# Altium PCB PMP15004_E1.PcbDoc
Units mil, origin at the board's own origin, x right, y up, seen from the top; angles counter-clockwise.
Board outline 993.36 x 993.36 mil, 2 copper layers (Top Layer, Bottom Layer), stack 62 mil thick; 37 components, 15 nets, 80 pads, 23 vias.
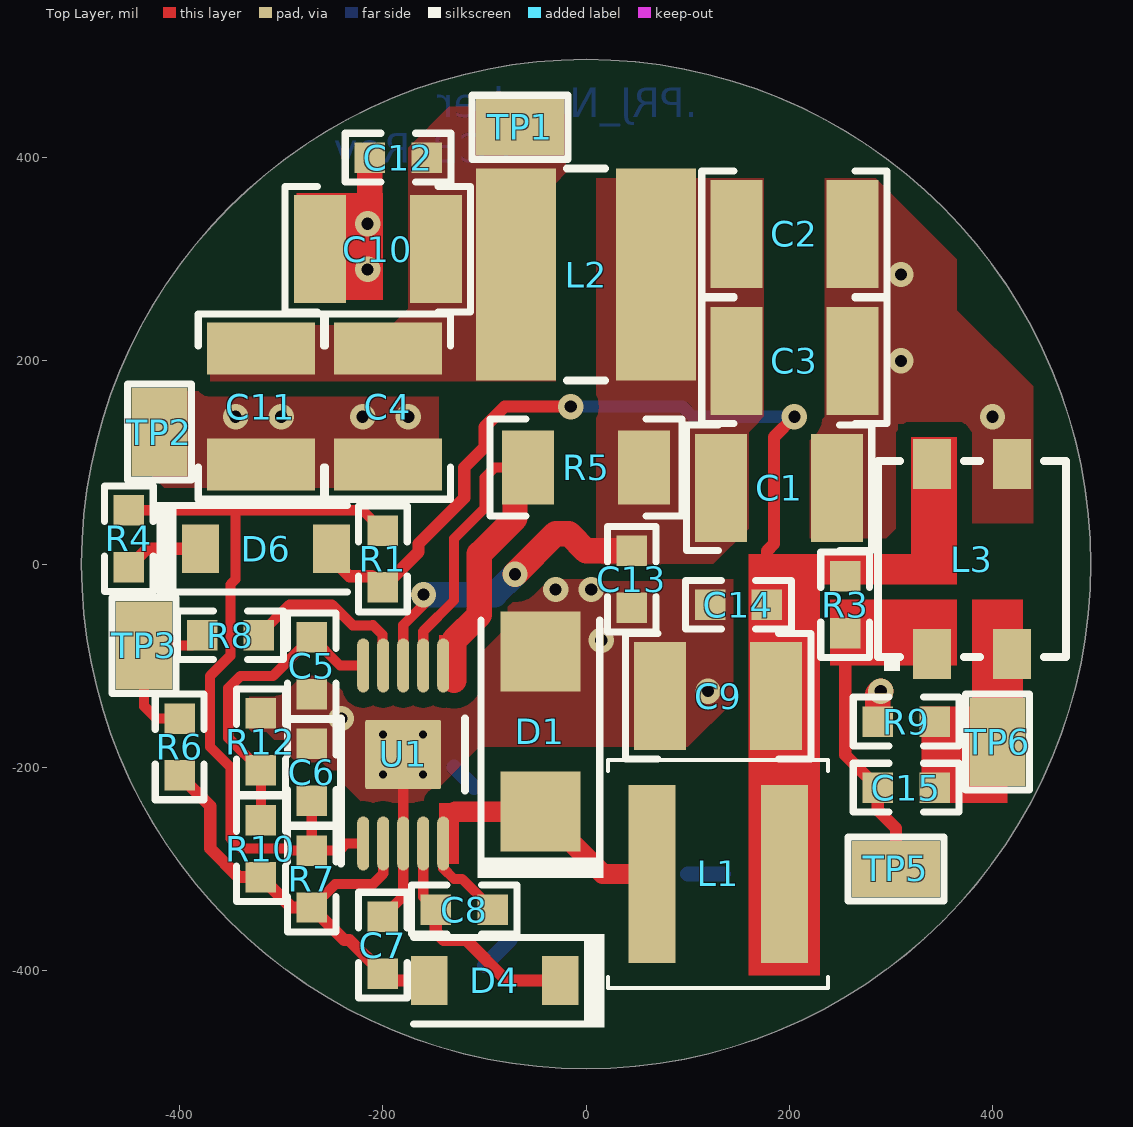
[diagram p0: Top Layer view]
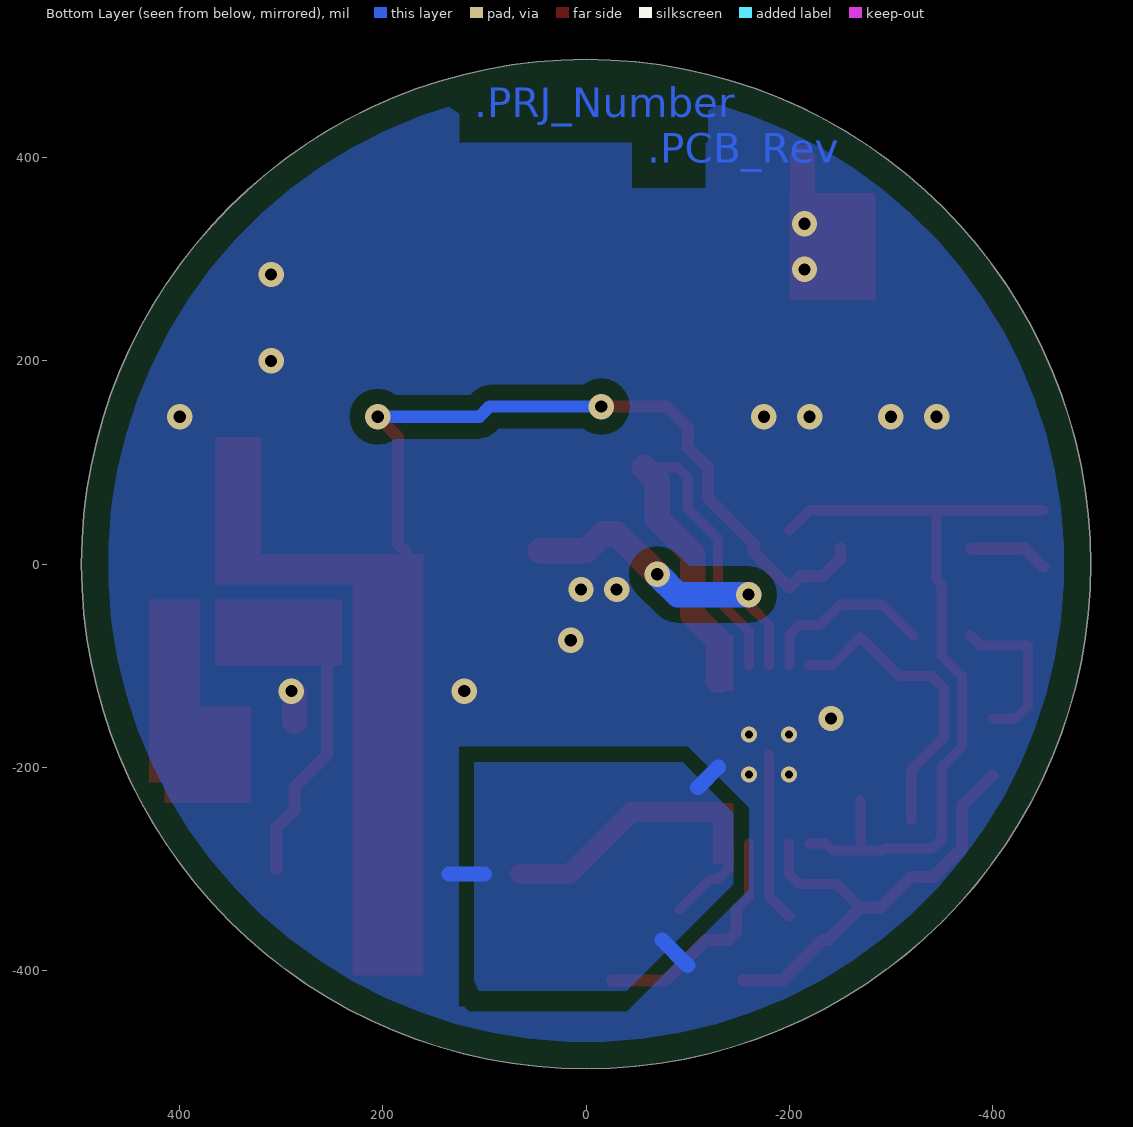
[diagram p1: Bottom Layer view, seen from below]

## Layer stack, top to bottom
Top Solder: solder mask 0.4, Solder Resist, Dk 3.5
Top Layer: signal copper 1.4
Dielectric1: core 59.2, FR-4, Dk 4.8
Bottom Layer: signal copper 1.4
Bottom Solder: solder mask 0.4, Solder Resist, Dk 3.5

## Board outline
0,-496.68 cw(c0,0) -496.68,0 cw(c0,0) 0,496.68 cw(c0,0) 496.68,0 cw(c0,0)

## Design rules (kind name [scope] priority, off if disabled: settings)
AcuteAngle [All] p1: minimum=4.50000000000000E+0001 checktracksonly=FALSE
AssemblyTestPointUsage [All] p1: valid=2
Clearance Clearance_BoardEdge [OnCopper and Not InComponentClass('Logo') and not InComponentClass('FiducialMark') and not InRegion(1000,500,4000,800) and Not IsKeepout vs IsKeepOut] p1: gap=15
Clearance Clearance_Poly [InPolygon] p2: gap=15
Clearance [All] p3: gap=7.87
ComponentClearance ComponentClearance_Logo [InComponentClass('Logo')] p1: gap=5 collisioncheckmode=3 verticalgap=10 showdistances=FALSE
ComponentClearance [All] p2: gap=5 collisioncheckmode=3 verticalgap=5 showdistances=FALSE
DiffPairsRouting [All] p1: maxlimit=100 minlimit=10 mostfreqgap=10 toplayer_minwidth=15 toplayer_maxwidth=15 toplayer_prefwidth=15 bottomlayer_minwidth=15 bottomlayer_maxwidth=15 bottomlayer_prefwidth=15 maxuncoupledlength=1000
FabricationTestPointUsage TestPointUsage [All] p1: valid=2 allowmultiple=FALSE
FabricationTestpoint Testpoint [All] p1: side=3 testpointundercomponent=TRUE minsize=40 maxsize=100 preferedsize=60 minholesize=0 maxholesize=40 preferedholesize=32 testpointgrid=1 allowsidetop=TRUE allowsidebottom=TRUE usegrid=TRUE gridtolerance=0.01
FanoutControl Fanout_LCC [IsLCC] p1: bgadir=Out bgaviamode=Centered fanoutstyle=Auto fanoutdirection=Alternating viagrid=1 // Fanout_LCC (Default Rule)
FanoutControl Fanout_BGA [IsBGA] p2: bgadir=Out bgaviamode=Centered fanoutstyle=Auto fanoutdirection=Alternating viagrid=1 // Fanout_BGA (Default Rule)
FanoutControl Fanout_Default [All] p4: bgadir=Out bgaviamode=Centered fanoutstyle=Auto fanoutdirection=Alternating viagrid=1 // Fanout_Default (Default Rule)
FanoutControl Fanout_Small [(CompPinCount < 5)] p5: bgadir=Out bgaviamode=Centered fanoutstyle=Auto fanoutdirection=OutThenIn viagrid=1 // Fanout_Small (Default Rule)
HoleSize [All] p1: absolutevalues=TRUE maxlimit=251 minlimit=7.87 maxpercent=80.000 minpercent=20.000
MinimumAnnularRing MinimumAnnularRing_ThermalPadVias [IsVia and InAnyComponent] p1: minimumring=3.94
MinimumAnnularRing [All] p2: minimumring=6.5
MinimumSolderMaskSliver MinimumSolderMaskSliver_Logo [InComponentClass('Logo') vs InComponentClass('Logo')] p1: minsoldermaskwidth=0.7
MinimumSolderMaskSliver [All] p2: minsoldermaskwidth=3.94
PlaneConnect [All] p1: planeconnectstyle=Relief reliefexpansion=10 reliefentries=4 reliefconductorwidth=10 reliefairgap=10
PolygonConnect PolygonConnect_direct [InNet('GND')or InNet('NetDRN_1')or InNet('VIN')or InNet('LED+')or InNet('NetRsense1_1')or InNet('NetR5_1')or InNet('NetC8_1')] p1: connectstyle=Direct reliefconductorwidth=10 reliefentries=4 polygonreliefangle="90 Angle" airgapwidth=10
PolygonConnect [All] p2: connectstyle=Direct reliefconductorwidth=10 reliefentries=4 polygonreliefangle="90 Angle" airgapwidth=10
RoutingVias [All] p1: holewidth=16 width=34 viastyle="Through Hole" minholewidth=7.87 minwidth=15.75 maxholewidth=40 maxwidth=65
SilkToBoardRegionClearance [Not ((IsComment or IsDesignator) And (Hide <> 'False')) and not InRegion(1000,500,4000,800)] p1:
SilkToSilkClearance SilkToSilkClearance_Pb-FreeLogo [(HasFootprint('Pb-Free_Overlay_Medium') OR HasFootprint('Pb-Free_Overlay_Small')) vs (HasFootprint('Pb-Free_Overlay_Medium') OR HasFootprint('Pb-Free_Overlay_Small'))] p1: silktosilkclearance=0
SilkToSilkClearance [All] p2: silktosilkclearance=4
SilkToSolderMaskClearance Inductors [IsPad] p1 off: minsilkscreentomaskgap=10 clearancetoexposedcopper=TRUE
SilkToSolderMaskClearance SilkToSolderMaskClearance_0603-095 [HasFootprint('0603_095')] p2 off: minsilkscreentomaskgap=1 clearancetoexposedcopper=TRUE
SilkToSolderMaskClearance SilkToSolderMaskClearance_discretes [IsPad AND InAnyComponent] p3 off: minsilkscreentomaskgap=5 clearancetoexposedcopper=TRUE
SilkToSolderMaskClearance [IsPad] p4 off: minsilkscreentomaskgap=5 clearancetoexposedcopper=TRUE
SilkToSolderMaskClearance "Silk to Solder Mask Opening" [IsVia vs InComponent('U1')] p5 off: minsilkscreentomaskgap=-1 clearancetoexposedcopper=FALSE
SolderMaskExpansion [All] p1: expansion=1.97
Width [All] p1: maxlimit=100 minlimit=6 preferedwidth=10 checkconnectedcopper=TRUE
15 further rules are at their usual default settings.

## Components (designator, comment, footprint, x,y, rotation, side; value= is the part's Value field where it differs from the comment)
C1 "GRM32ER71J106KA12L" 1210 190,75 r0 top
C2 "GRM32ER71J106KA12L" 1210 205,325 r0 top
C3 "GRM32ER71J106KA12L" 1210 205,200 r0 top
C4 "GRM32ER71J106KA12L" 1210 -195,155 r270 top
C5 "GCM188R71C104KA37J" 0603_HV -270,-100 r90 top
C6 "GCM1885C1H471JA16D" 0603_HV -270,-205 r90 top
C7 "GCM188R71C105KA64D" 0603_HV -200,-375 r90 top
C8 "GCM188R71C104KA37J" 0603_HV -120,-340 r180 top
C9 "CGA5L3X7S2A225M160AB" 1210 130,-130 r180 top
C10 "GRM32ER71J106KA12L" 1210 -205,310 r180 top
C11 "GRM32ER71J106KA12L" 1210 -320,155 r270 top
C12 "GRM188R72A104KA35D" 0603_HV -185,400 r180 top
C13 "GRM188R72A104KA35D" 0603_HV 45,-15 r270 top
C14 "GRM188R71E104KA01D" 0603_HV 150,-40 r180 top
C15 "GRM188R71E104KA01D" 0603_HV 315,-220 r0 top
D1 "RB058L-60TE25" SMA -45,-165 r90 top
D4 "MMSD4148T1G" SOD-123 -90,-410 r180 top
D6 "MMSD4148T1G" SOD-123 -315,15 r0 top
L1 "XAL5050-223MEB" XAL5050 130,-305 r0 top
L2 "74408943100" WE-SPC_4838 0,285 r0 top
L3 "ACM4520-421-2P-T000" TDK_ACM4520 379.71,5 r90 top
R1 "CRCW060324K9FKEA" 0603_HV -200,5 r90 top
R3 "CRCW06030000Z0EA" 0603_HV 255,-40 r270 top
R4 "CRCW060348K7FKEA" 0603_HV -450,25 r270 top
R5 "WSL1206R1500FEA" 1206 0,95 r0 top
R6 "CRCW060310K0FKEA" 0603_HV -400,-180 r90 top
R7 "CRCW0603309KFKEA" 0603_HV -270,-310 r90 top
R8 "CRCW060310K0FKEA" 0603_HV -350,-70 r0 top
R9 "CRCW06030000Z0EA" 0603_HV 315,-155 r0 top
R10 "CRCW0603100KFKEA" 0603_HV -320,-280 r270 top
R12 "CRCW060361K9FKEA" 0603_HV -320,-175 r270 top
TP1 "5015" S2751-46R -65,430 r0 top
TP2 "5015" S2751-46R -420,130 r270 top
TP3 "5015" S2751-46R -435,-80 r90 top
TP5 "5015" S2751-46R 305,-300 r180 top
TP6 "5015" S2751-46R 405,-175 r270 top
U1 "TPS92515HVQDGQRQ1" DGQ0010A_N -180,-187.4 r90 top

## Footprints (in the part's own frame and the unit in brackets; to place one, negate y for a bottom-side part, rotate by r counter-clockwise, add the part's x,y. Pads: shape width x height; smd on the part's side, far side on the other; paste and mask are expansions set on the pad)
0603_HV [mil] "Ernesto recommended land pattern.  26 mil between pads."
  rect 30x30 smd: 1(-28,0) 2(28,0)
  silkscreen extent -52,-24 52,24, body extent -34,-19 34,19, height 39
1206 [mm] "1206 from SM-752 data"
  rect 1.3x1.85 smd: 1(-1.45,0) 2(1.45,0)
  silkscreen extent -2.4,-1.21 2.4,1.21, body extent -1.7,-0.9 1.7,0.9, height 1.35
1210 [mm] "1210 from SM-752 data"
  rect 1.3x2.7 smd: 1(-1.45,0) 2(1.45,0)
  silkscreen extent -2.32,-1.57 2.32,1.57, body extent -1.7,-1.35 1.7,1.35, height 1.35
DGQ0010A_N [mm] "TSSOP, 10-Leads, Body 3x3mm, Pitch 0.5mm, Exposed Pad, IPC Medium Density"
  rrect100% 1.35x0.3 smd: 1(-2.225,1) 2(-2.225,0.5) 3(-2.225,0) 4(-2.225,-0.5) 5(-2.225,-1) 6(2.225,-1) 7(2.225,-0.5) 8(2.225,0) 9(2.225,0.5) 10(2.225,1)
  rrect6% 1.73x1.9 smd: 11(0,0)
  silkscreen extent -2.73,-1.55 0.9,1.55, body extent -2.45,-1.5 2.45,1.5, height 0.96
S2751-46R [mm] "Harwin P/N S2751-46R"
  rect 2.2x1.4 smd: 1(0,0)
  silkscreen extent -1.2,-0.8 1.2,0.8, body extent -1,-0.6 1,0.6, height 1.41
SMA [mm] "Molded Diode, 2-Leads, Body 4.3x2.6mm, IPC Medium Density, based on OnSemi component dimensions and land pattern"
  rect 2x2 smd: 1(-2,0) 2(2,0)
  silkscreen extent -3.66,-1.57 2.79,1.57, body extent -2.6,-1.3 2.6,1.3, height 2.42
SOD-123 [mm] "On Semi recommended land pattern"
  rect 0.915x1.22 smd: 1(-1.637,0) 2(1.637,0)
  silkscreen extent -2.74,-1.17 2.03,1.17, body extent -1.93,-0.9 1.93,0.9, height 1.35
TDK_ACM4520 [mm] "SMD, 4-Leads, Body 4.7x4.5mm"
  rect 1.25x0.95 smd: 1(-2.375,1) 2(-2.375,-1) 3(2.375,-1) 4(2.375,1)
  silkscreen extent -2.8,-2.35 2.45,2.35, body extent -2.45,-2.35 2.45,2.35, height 2
WE-SPC_4838 [mm] "WURTH"
  rect 2x5.3 smd: 1(-1.75,0) 2(1.75,0)
  silkscreen extent -0.48,-2.65 0.48,2.65, body extent -2.55,-2.55 2.55,2.55, height 4.1
XAL5050 [mm] "CoilCraft XAL5050 5.28 x 5.48 x 5.1 mm"
  rect 1.18x4.44 smd: 1(-1.655,0) 2(1.655,0)
  silkscreen extent -2.75,-2.85 2.75,2.85, body extent -2.74,-2.84 2.74,2.84, height 5.1

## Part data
C1 C2 C3 C4 C10 C11: "CAP, CERM, 10 µF, 63 V, +/- 10%, X7R, 1210"
C5 C8: "CAP, CERM, 0.1 µF, 16 V, +/- 10%, X7R, 0603_095"
C6: "CAP, CERM, 470 pF, 50 V, +/- 5%, C0G/NP0, 0603_095"
C7: "CAP, CERM, 1 µF, 16 V, +/- 10%, X7R, 0603_095"
C9: "CAP, CERM, 2.2 µF, 100 V, +/- 20%, X7S, 1206_190"
C12 C13: "CAP, CERM, 0.1 µF, 100 V, +/- 10%, X7R, 0603"
C14 C15: "CAP, CERM, 0.1 µF, 25 V, +/- 10%, X7R, 0603"
D1: library part Diode_Schottky, "Diode, Schottky, 60V, 3A, SMA"
D4 D6: "Diode, Switching, 100 V, 0.2 A, SOD-123"
L1: "Inductor, Shielded, Composite, 22 µH, 3.4 A, 0.1 ohm, SMD"
L2: "Inductor, Shielded Drum Core, Ferrite, 10 µH, 1.65 A, 0.082 ohm, SMD"
L3: "Coupled inductor, 2.8 A, 0.055 ohm, SMD"
R1: "RES, 24.9 k, 1%, 0.1 W, 0603"
R3 R9: "RES, 0, 5%, 0.1 W, 0603"
R4: "RES, 48.7 k, 1%, 0.1 W, 0603"
R5: "RES, 0.15, 1%, 0.25 W, 1206"
R6 R8: "RES, 10.0 k, 1%, 0.1 W, 0603"
R7: "RES, 309 k, 1%, 0.1 W, 0603"
R10: "RES, 100 k, 1%, 0.1 W, 0603"
R12: "RES, 61.9 k, 1%, 0.1 W, 0603"
TP1 TP2 TP3 TP5 TP6: "Test Point, Miniature, SMT"
U1: library part TPS92515QDGQRQ1, "2A, 65V, Automotive Buck LED Driver with Integrated N-FET, DGQ0010A"

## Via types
v1: diameter 25, hole 12, Top Layer to Bottom Layer, 19 vias
v2: diameter 15.75, hole 7.87, Top Layer to Bottom Layer, 4 vias

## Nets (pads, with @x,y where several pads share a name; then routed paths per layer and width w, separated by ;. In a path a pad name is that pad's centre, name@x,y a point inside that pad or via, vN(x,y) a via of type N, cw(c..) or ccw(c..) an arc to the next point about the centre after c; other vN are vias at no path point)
GND: C1.2 C2.2 C3.2 C4.2 C5.1 C6.2 C7.2 C9.2 C10.2 C11.2 C12.2 C13.2 C14.2 D1.2 L3.3 R9.1 R12.1 TP2.1 U1.3 U1.11 | length 363.6
  Top Layer w10: C7.2 -180,-327 U1.3 U1.11
  Top Layer w25: v1(-215,335) -213,337 C12.2 ; R9.1 287,-128 v1(290,-125)
  Bottom Layer w15: -130,-200 -110,-220 ; -100,-395 -75,-370 ; 100,-305 135,-305
  other v1: -241.02,-151.97 120,-125 15,-75 -30,-25 5,-25 -345,145 -300,145 -220,145 -175,145 400,145 310,200 310,285 -215,290
  other v2: -199.68,-207.09 -160.31,-207.09 -199.68,-167.72 -160.31,-167.72
IADJ: C5.2 R10.1 R12.2 U1.10 | length 308.2
  Top Layer w10: R10.1 R12.2 -352.13,-170.87 -352.13,-122.13 -340,-110 -308,-110 C5.2 -242.2,-99.8 U1.10
LED+: C9.1 C14.1 D6.2 L1.2 L3.4 R1.1 R3.1 | length 784.8
  Top Layer w12: D6.2 -250.53,5.53 -233,-12 -211,-12 R1.1 -165,12 -165,20 -120,65 -120,95 -100,115 -100,135 -80,155 v1(-15,155) ; C14.1 178,13 185,20 185,125 v1(205,145)
  Bottom Layer w12: v1(-15,155) 95,155 105,145 v1(205,145)
NetC4_1: C4.1 C10.1 C11.1 C12.1 L2.1 TP1.1
NetC6_1: C6.1 R1.2 R4.1 R7.2 U1.1 | length 787.7
  Top Layer w10: R4.1 -345,53 ; C6.1 R7.2 ; U1.1 -236.02,-275 -243.02,-282 R7.2 ; R1.2 -220,53 -345,53 ; -345,53 -345,-15 -350,-20 -350,-90 -350.13,-90.13 -350.13,-90.33 -369.79,-110 -370,-110 -370,-180 -350,-200 -350,-270.21 -340.21,-280 -294,-280 -292,-282 R7.2
NetC8_1: C8.1 D1.1 L1.1 U1.5 | length 308.8
  Top Layer w10: U1.5 -140.63,-299.37 -130,-310 -122,-310 C8.1
  Top Layer w20: -128.74,-243.74 D1.1 16.26,-305 L1.1
NetC8_2: C8.2 D4.1 U1.4 | length 234.5
  Top Layer w10: U1.4 -160.32,-327.69 C8.2
  Top Layer w12: C8.2 -148,-362 -140,-370 -118,-370 -78,-410 D4.1
NetC15_1: C15.1 L3.1 R3.2 TP5.1 | length 252.7
  Top Layer w12: R3.2 255,-188 C15.1 287,-242 305,-260 TP5.1
NetC15_2: C15.2 L3.2 R9.2 TP6.1
NetD6_1: D6.1 R4.2 | length 78
  Top Layer w12: R4.2 -432,15 D6.1
NetR5_1: R5.1 U1.6 U1.7 | length 496.7
  Top Layer w10: U1.7 -160.32,-66.2 -130,-35.88 -130,25 -100,55 -100,85 -90,95 R5.1
  Top Layer w25: -130,-114.63 -130,-75 -105,-50 -105,10 -70,45 -70,82.09 R5.1
NetR6_2: R6.2 R8.1 TP3.1 | length 161.1
  Top Layer w10: R6.2 -423,-152 -435,-140 TP3.1 -388,-80 R8.1
NetR8_2: R8.2 U1.9 | length 176.6
  Top Layer w10: R8.2 -292,-40 -250,-40 -229.65,-60.35 -210.35,-60.35 ; -210,-60 -200.37,-69.63 -200.37,-99.11 U1.9
VCC: C7.1 D4.2 R6.1 R7.1 R10.2 U1.2 | length 467.6
  Top Layer w10: R7.1 -247,-315 -210,-315 -199.69,-304.69 U1.2
  Top Layer w12: R6.1 -370,-238 -370,-280 -342,-308 R10.2 -290,-338 R7.1 -238,-370 -233,-370 C7.1 -193,-410 D4.2
VIN: C1.1 C2.1 C3.1 C13.1 L2.2 R5.2 U1.8 | length 315
  Top Layer w10: U1.8 -180,-60 -160,-40 v1(-160,-30)
  Top Layer w25: v1(-70,-10) -30,30 -17,30 0,13 C13.1
  Bottom Layer w25: v1(-160,-30) -90,-30 v1(-70,-10)

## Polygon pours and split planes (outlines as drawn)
GND on Bottom Layer "GND_L02_P021" (solid, remove dead copper, pour order 21): -95,-195 -145,-245 -145,-315 -40,-420 105,-420 105,-195
GND on Bottom Layer "GND_L02_P019" (solid, remove dead copper, pour order 19): 0,-470.03 cw(c0,0) -470.03,0 cw(c0,0) 0,470.03 cw(c0,0) 470.03,0 cw(c0,0)
VIN on Top Layer "VIN_L01_P029" (solid, remove dead copper, pour order 29): 30,0 125,0 160,35 160,130 175,145 175,380 10,380 10,0
GND on Top Layer "Bottom Layer-No Net" (solid, remove dead copper, pour order 23): -335,-130 -305,-130 -285,-110 -255,-110 -230,-135 -215,-135 -120,-135 -110,-125 -105,-120 -105,-95 -105,-85 -85,-65 -85,-40 -75,-30 -60,-15 65,-15 145,-15 145,-135 100,-180 -105,-180 -145,-220 -160,-235 -195,-235 -220,-235 -245,-210 -260,-195 -285,-195 -315,-165 -335,-165
GND on Top Layer "GND_L01_P031" (solid, remove dead copper, pour order 31): 380,40 440,40 440,175 365,250 365,300 285,380 235,380 235,145 220,130 220,25 295,25 305,35 305,130 315,140 370,140 380,130
NetC4_1 on Top Layer "NETC4_1_L01_P033" (solid, remove dead copper, pour order 33): -175,180 -30,180 -30,375 -20,385 -20,450 -135,450 -175,410 -175,251.2 -191.2,235 -370,235 -370,180
GND on Top Layer "Bottom Layer-No Net" (solid, remove dead copper, pour order 35): -445,170 -145,170 -145,75 -415,75 -445,105

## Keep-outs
Keep-Out Layer:
  text ".Layer_Name" at -173,-1608.49 h60

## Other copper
Top Layer:
  rectangle net NetR5_1: -145,-125 -125,-70
  rectangle net NetC8_1: -145,-295 -125,-235
  rectangle net LED+: 160,-405 230,10
  rectangle net LED+: 320,-20 365,125
  rectangle net LED+: 210,-20 365,10
  rectangle net NetC15_1: 240,-100 365,-35
  rectangle net NetC15_2: 380,-215 430,-35
  rectangle net NetC15_2: 330,-235 415,-140
  rectangle net GND: -285,260 -200,365
  text ".Layer_Name" at -173,-1608.49 h60
Bottom Layer:
  pour cut-out: 125,-435 125,-180 -100,-180 -160,-240 -160,-320 -40,-440 115,-440 115,-420 -40,-420 -145,-315 -145,-245 -95,-195 110,-195 110,-410 120,-420 120,-435
  text ".PRJ_Number" at 110,430 h50
  text ".PCB_Rev" at -60,385 h50
  text ".Layer_Name" at -173,-1608.49 h60

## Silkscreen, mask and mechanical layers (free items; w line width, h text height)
Top Overlay:
  text ".Layer_Name" at -173,-1608.49 h60
Bottom Overlay:
  text ".Layer_Name" at -173,-1608.49 h60
Top Paste:
  text ".Layer_Name" at -173,-1608.49 h60
Bottom Paste:
  text ".Layer_Name" at -173,-1608.49 h60
Top Solder:
  text ".Layer_Name" at -173,-1608.49 h60
  text ".Layer_Name" at -173,-1608.49 h60
Bottom Solder:
  text ".Layer_Name" at -173,-1608.49 h60
Drill Guide:
  text ".Layer_Name" at -173,-1608.49 h60
M1 Board Outline:
  circle w7: c0,0 r496.68
  text ".Layer_Name" at -173,-1608.49 h60
M2 Board Dimensions:
  lines w1: 0,0 470,470 785,470
  text "R 0.497in" at 815,450 h40
  text ".Layer_Name" at -173,-1608.49 h60
M3 3D STEP Top:
  text ".Layer_Name" at -173,-1608.49 h60
M4 3D STEP Bottom:
  text ".Layer_Name" at -173,-1608.49 h60
M5 Assembly Top:
  lines w10: -1042,-1680.17 5558,-1680.17 ; -1042,-1476.83 5560,-1476.83 ; -1042,-1273.5 -1042,-1883.5 2963,-1883.5 5560,-1883.5 5560,-1273.5 -1041.5,-1273.5 -1041.5,-1883.5 534,-1883.5 ; 1423,-1883.5 1423,-1273.5 ; 2690,-1476.83 2690,-1273.5 ; 3530,-1476.83 3530,-1273.5 ; 4152,-1890 4152,-1687.17
  text "COMPONENTS MARKED 'DNP' SHOULD NOT BE POPULATED." at 403.5,-1068.5 h60
  text "ASSEMBLY VARIANT:" at 403,-1184 h60
  text ".VariantName" at 1439,-1184 h60
  text "PCB VIEWED FROM TOP SIDE" at -978.5,-1405.67 h60
  text "BOARD #:" at 1498,-1405.67 h60
  text ".PRJ_Number" at 2043.5,-1405.67 h60
  text "REV:" at 2888,-1405.67 h60
  text ".PCB_Rev" at 3179.5,-1405.67 h60
  text "SVN REV:" at 3726,-1405.67 h60
  text ".VersionControl_RevNumber" at 4232,-1405.67 h60
  text "TID #:" at 1498,-1609 h60
  text ".TID" at 2043.5,-1609 h60
  text "PLOT NAME =" at -978.5,-1814.34 h60
  text ".plot_File_Name" at -173,-1814.34 h60
  text "GENERATED    :" at 1500,-1814.34 h60
  text ".Print_Date" at 2369.5,-1814.34 h60
  text ".Print_Time" at 3098.5,-1814.34 h60
  text "TEXAS INSTRUMENTS" at 4363,-1814.34 h60
M6 Assembly Bottom:
  lines w10: -1042.5,-1477.33 5559.5,-1477.33 ; -1040.5,-1680.67 5559.5,-1680.67 ; 365.5,-1890.5 365.5,-1687.67 ; 987.5,-1477.33 987.5,-1274 ; 1827.5,-1477.33 1827.5,-1274 ; 3094.5,-1884 3094.5,-1274 ; 3983.5,-1884 5559,-1884 5559,-1274 -1042.5,-1274 -1042.5,-1884 1554.5,-1884 5559.5,-1884 5559.5,-1274
  text "COMPONENTS MARKED 'DNP' SHOULD NOT BE POPULATED." at 5352,-1068 h60
  text ".VariantName" at 4308,-1184 h60
  text "ASSEMBLY VARIANT:" at 5347,-1184 h60
  text ".VersionControl_RevNumber" at 285.5,-1406.17 h60
  text "SVN REV:" at 791.5,-1406.17 h60
  text ".PCB_Rev" at 1338,-1406.17 h60
  text "REV:" at 1629.5,-1406.17 h60
  text ".PRJ_Number" at 2474,-1406.17 h60
  text "BOARD #:" at 3019.5,-1406.17 h60
  text "PCB VIEWED FROM BOTTOM SIDE" at 5496,-1406.17 h60
  text ".TID" at 2474,-1609.5 h60
  text "TID #:" at 3019.5,-1609.5 h60
  text "TEXAS INSTRUMENTS" at 154.5,-1814.84 h60
  text ".Print_Time" at 1419,-1814.84 h60
  text ".Print_Date" at 2148,-1814.84 h60
  text "GENERATED    :" at 3017.5,-1814.84 h60
  text ".plot_File_Name" at 4690.5,-1814.84 h60
  text "PLOT NAME =" at 5496,-1814.84 h60
M9 Title Sheet:
  drawing of 57 lines, arcs and shapes, not listed
  text "1" at -10.16,7286.5 h70
  text "2" at 2485.5,7286.5 h70
  text "3" at 4974.84,7286.5 h70
  text "4" at 7481.51,7286.5 h70
  text "5" at 9980.5,7286.5 h70
  text "6" at 12485.5,7286.5 h70
  text "A" at -1166.5,6143.5 h70
  text "A" at 13633.5,6143.5 h70
  text "B" at -1166.5,3763.5 h70
  text "B" at 13633.5,3763.5 h70
  text "C" at -1166.5,1388.5 h70
  text "C" at 13633.5,1388.5 h70
  text "PROJECT TITLE:" at 10593.5,-472.5 h45
  text ".PRJ_Title" at 10643.5,-605.83 h70
  text "DESIGNED FOR:" at 10593.5,-773.5 h45
  text ".PRJ_Customer" at 10643.5,-913.5 h70
  text "D" at -1166.5,-981.5 h70
  text "D" at 13633.5,-981.5 h70
  text "FILE NAME:" at 10593.5,-1073.5 h45
  text ".PCB_File_Name_No_Path" at 10643.5,-1193.5 h70
  text "Texas Instruments (TI) and/or its licensors do not warrant the accuracy or completeness of this specification" at 5624,-1355.34 h45
  text "ENGINEER:" at 10593.5,-1363.5 h45
  text "LAYOUT BY:" at 12098.5,-1363.5 h45
  text "or any information contained therein. TI and/or its licensors do not warrant that this design will meet" at 5579.01,-1468 h45
  text ".PRJ_Engineer" at 10643.5,-1518.49 h70
  text ".PCB_Layout" at 12149,-1518.49 h70
  text "the specifications, will be suitable for your application or fit for any particular purpose, or will operate in" at 5579.01,-1580.67 h45
  text ".Layer_Name" at -173,-1608.49 h60
  text "ALTIUM DESIGNER VERSION:" at 12098.5,-1673.5 h45
  text "an implementation. TI and/or its licensors do not warrant that the design is production worthy. You should" at 5579.01,-1693.33 h45
  text "completely validate and test your design implementation to confirm the system functionality for your application." at 5624,-1806 h45
  text ".print_Scale" at 10643.5,-1806.83 h70
  text ".Application_BuildNumber" at 12149,-1806.83 h70
  text "1" at -10.16,-2013.5 h70
  text "2" at 2485.5,-2013.5 h70
  text "3" at 4974.84,-2013.5 h70
  text "4" at 7481.51,-2013.5 h70
  text "5" at 9980.5,-2013.5 h70
  text "6" at 12485.5,-2013.5 h70
M10 Fab Notes:
  drawing of 185 lines, arcs and shapes, not listed
  text "DESIGN INFORMATION" at 11631.02,5160 h60
  text "MIN. TRACK WIDTH:" at 10986.46,4980 h60
  text "10" at 12082.7,4980 h60
  text "MIL" at 12237.46,4980 h60
  text "MIN. CLEARANCE:" at 10986.46,4848 h60
  text "0.2" at 12022.7,4848 h60
  text "MM" at 12237.46,4848 h60
  text "MIN. VIA PAD SIZE:" at 10986.46,4716 h60
  text "25" at 12052.71,4716 h60
  text "MIL" at 12237.46,4716 h60
  text "MINIMUM ANNULAR RING" at 10657.23,4570 h60
  text "EXTERNAL" at 12389.46,4570 h60
  text "PER ORDER" at 11787.42,4560.64 h60
  text "PER" at 10857.23,4452 h60
  text "IPC-D-275 CLASS 2 LEVEL C" at 11077.23,4452 h60
  text "PER ORDER" at 13005.42,4334.64 h60
  text "REGISTRATION TOLERANCES:" at 10657.23,4334 h60
  text "METAL" at 11857,4334 h60
  text "PER ORDER" at 12162,4334 h60
  text "HOLES" at 12706,4328 h60
  text "MATERIAL:" at 10582.46,4124.54 h60
  text "FR-4 High Tg" at 11568.9,3984.21 h60
  text "FR-408" at 11003.46,3975.64 h60
  text "OTHER" at 12491.46,3975.64 h60
  text "X" at 11410,3965 h60
  text "62 MIL (1.6mm) +/-10%" at 11323.56,3812.92 h60
  text "THICKNESS:" at 10657.23,3808.64 h60
  text "X" at 11195.4,3808.64 h60
  text "OTHER" at 12608.46,3808.64 h60
  text "TOLERANCE:" at 10657.23,3650.64 h60
  text "ANSI IPC-6012 TYPE 3 CLASS 2" at 11683.48,3650.64 h60
  text "X" at 11493,3501 h60
  text "OTHER +/-" at 11683.46,3494.64 h60
  text "PER ORDER" at 12320.42,3484.64 h60
  text "BOW & TWIST:" at 10657.23,3337.64 h60
  text "ANSI IPC-6012 TYPE 3 CLASS 2" at 11683.48,3337.64 h60
  text "PER ORDER" at 12325.42,3184.64 h60
  text "OTHER +/-" at 11683.46,3179.13 h60
  text "X" at 11499,3178 h60
  text "DRILLING:" at 10582.46,3040.64 h60
  text "REFERENCE:" at 10657.23,2923.64 h60
  text "X" at 11305.46,2923.64 h60
  text "AS SHOWN" at 11492.46,2923.64 h60
  text "X" at 12206.46,2923.64 h60
  text "NC_DRILL FILES" at 12343.46,2923.64 h60
  text "PTH MIN COPPER THICKNESS:" at 10657.23,2765.64 h60
  text "X" at 12007.46,2765.64 h60
  text "1MIL" at 12144.46,2765.64 h60
  text "OTHER" at 12641.46,2765.64 h60
  text "BOARD FINISH:" at 10582.46,2606.64 h60
  text "SILKSCREEN:" at 10737.68,2488.64 h60
  text "X" at 11686.46,2488.64 h60
  text "TOP" at 11812.46,2488.64 h60
  text "BOTTOM" at 12323.46,2488.64 h60
  text "SILKSCREEN COLOR:" at 10737.68,2321.64 h60
  text "X" at 11685.42,2321.64 h60
  text "WHITE" at 11812.46,2321.64 h60
  text "OTHER" at 12323.46,2321.64 h60
  text "SOLDER RESIST COLOR:" at 10737.68,2151.64 h60
  text "X" at 11305.42,1992.44 h60
  text "GREEN" at 11432.46,1992.44 h60
  text "BLUE" at 12023.46,1992.44 h60
  text "OTHER" at 12561.46,1992.44 h60
  text "IMMERSION GOLD (ENIG)" at 11643.46,1803.92 h60
  text "ENEPIG" at 12981,1800.64 h60
  text "SURFACE FINISH:" at 10582.46,1799.64 h60
  text "IMM. TIN/SILVER OR EQUIV" at 10912,1642.64 h60
  text "OTHER" at 12343.46,1642.64 h60
  text "X" at 10742.5,1630 h60
  text "X" at 11449,1473 h60
  text "ARRAY/PANEL:" at 10582.46,1463.64 h60
  text "CUT AND TRIM PER MECH LAYER 1" at 11643.46,1459.35 h60
  text "N.C. ROUTE" at 11643.46,1307.64 h60
  text "V. SCORE" at 12509.46,1307.64 h60
  text "CERTIFICATION:" at 10582.46,1170.64 h60
  text "MATERIALS AND WORKMANSHIP FOR ALL PCBS" at 11307.46,1170.64 h60
  text "TO MEET OR EXCEED THE REQUIREMENTS OF:" at 11307.46,1072.64 h60
  text "X" at 10933.96,936.13 h60
  text "ANSI IPC-A-600F CLASS ->" at 11072.96,936.13 h60
  text "X" at 12712.02,936.13 h60
  text "2" at 12830.96,936.14 h60
  text "1" at 12515.96,934.64 h60
  text "3" at 13184.96,934.64 h60
  text "UL 94V-0" at 11072.96,776.64 h60
  text "X" at 11748.02,776.64 h60
  text "RoHS" at 11884.96,776.64 h60
  text "OTHER" at 12529.36,776.64 h60
  text "X" at 10925,775 h60
  text "ADDITIONAL REQUIREMENTS:" at 10582.46,635.64 h60
  text "MICROSECTION:" at 10657.23,520.64 h60
  text "YES" at 11562.96,520.64 h60
  text "X" at 11822,376 h60
  text "REQUIRED" at 12424.46,364.49 h60
  text "BARE BOARD ELEC. TEST:" at 10657.23,361.64 h60
  text "NONE" at 11962.96,361.64 h60
  text "PER ORDER" at 13016.46,361.64 h60
  text "MANUFACTURER'S UL:" at 10657.23,204.64 h60
  text "RAIL" at 11822.96,200.35 h60
  text "METAL" at 12314.77,200.35 h60
  text "X" at 12690,200 h60
  text "SILK" at 12826.46,200.35 h60
  text ".Layer_Name" at -173,-1608.49 h60
M11 Gerber Information:
  lines w10: -1042,-1680.17 5558,-1680.17 ; -1042,-1476.83 5560,-1476.83 ; -1042,-1273.5 -1042,-1883.5 2963,-1883.5 5560,-1883.5 5560,-1273.5 -1041.5,-1273.5 -1041.5,-1883.5 534,-1883.5 ; 1423,-1883.5 1423,-1273.5 ; 2690,-1476.83 2690,-1273.5 ; 3530,-1476.83 3530,-1273.5 ; 4152,-1890 4152,-1687.17
  text "ALL ARTWORK VIEWED FROM TOP SIDE" at -978.5,-1405.67 h60
  text "BOARD #:" at 1498,-1405.67 h60
  text ".PRJ_Number" at 2043.5,-1405.67 h60
  text "REV:" at 2888,-1405.67 h60
  text ".PCB_Rev" at 3179.5,-1405.67 h60
  text "SVN REV:" at 3726,-1405.67 h60
  text ".VersionControl_RevNumber" at 4232,-1405.67 h60
  text "LAYER NAME =" at -978.5,-1608.49 h60
  text "TID #:" at 1498,-1609 h60
  text ".TID" at 2043.5,-1609 h60
  text "PLOT NAME =" at -978.5,-1814.34 h60
  text ".plot_File_Name" at -173,-1814.34 h60
  text "GENERATED    :" at 1500,-1814.34 h60
  text ".Print_Date" at 2369.5,-1814.34 h60
  text ".Print_Time" at 3098.5,-1814.34 h60
  text "TEXAS INSTRUMENTS" at 4363,-1814.34 h60
M12 Stackup:
  text ".Layer_Name" at -173,-1608.49 h60
M13 Component Bodies Top:
  text ".Layer_Name" at -173,-1608.49 h60
M14 Component Bodies Bottom:
  text ".Layer_Name" at -173,-1608.49 h60
M15 Courtyards Top:
  text ".Layer_Name" at -173,-1608.49 h60
M16 Courtyards Bottom:
  text ".Layer_Name" at -173,-1608.49 h60
Drill Drawing:
  circle w10: c4933.82,2391.52 r27.67
  lines w10: 4906.16,2488.35 4933.82,2502.18 4961.49,2488.35 4947.66,2516.02 4961.49,2543.68 4933.82,2529.85 4906.16,2543.68 4919.99,2516.02 4906.16,2488.35 ; 4917.23,2499.42 4933.82,2507.72 4950.43,2499.42 4942.12,2516.02 4950.43,2532.62 4933.82,2524.32 4917.23,2532.62 4925.52,2516.02 4917.23,2499.42
  lines w12: 4856,2326.5 6834.44,2326.5 ; 4856,2575.5 6834.44,2575.5 ; 5194.01,2202 5194.01,2700 ; 5526.17,2202 5526.17,2700 ; 6162.65,2202 6162.65,2700 ; 6421.85,2202 6421.85,2700 ; 4856,2202 6834.44,2202 6834.44,2700 4856,2700 4856,2202
  text "Symbol" at 4930.7,2612.85 h72
  text "Quantity" at 5231.36,2612.85 h72
  text "Finished Hole Size" at 5563.52,2612.85 h72
  text "Plated" at 6200,2612.85 h72
  text "Hole Type" at 6459.2,2612.85 h72
  text "4" at 5231.36,2488.35 h60
  text "7.87mil (0.200mm)" at 5563.52,2488.35 h60
  text "PTH" at 6200,2488.35 h60
  text "Round" at 6459.2,2488.35 h60
  text "19" at 5231.36,2363.85 h60
  text "12.00mil (0.305mm)" at 5563.52,2363.85 h60
  text "PTH" at 6200,2363.85 h60
  text "Round" at 6459.2,2363.85 h60
  text "23 Total" at 5231.36,2239.35 h60
  text ".Layer_Name" at -173,-1608.49 h60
